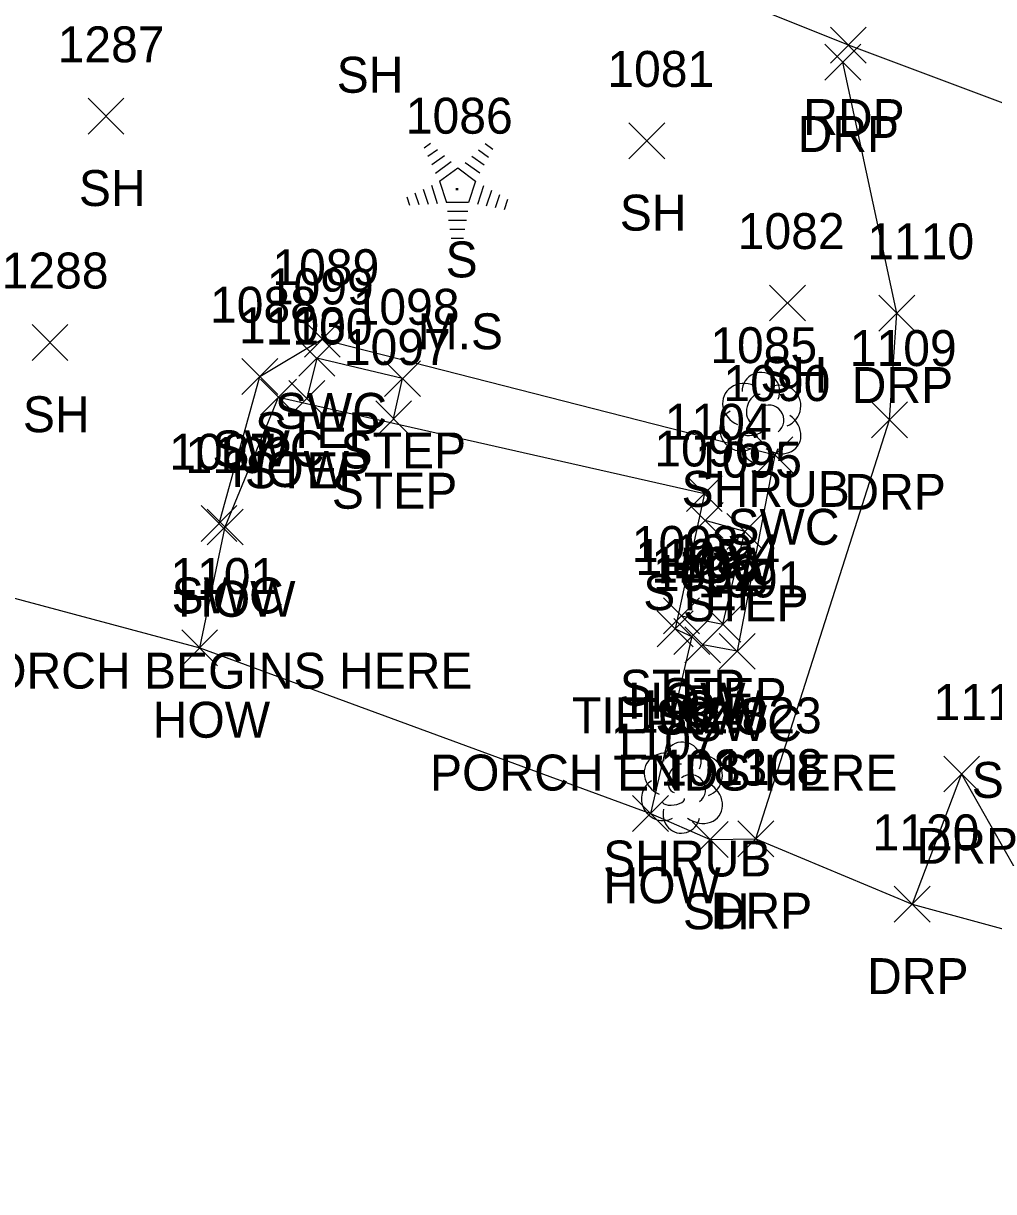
# Model space of a CAD drawing. Extents: x 1616726 to 1619875, y 273782 to 276557.
# Drawn here: x 1617145 to 1617199, y 276075.1 to 276140.1 of the extents above; entities that cross this region are included whole.
import ezdxf

# ---------------------------------------------------------------- set-up
doc = ezdxf.new("R2010")
doc.units = 0
for name, color, linetype in [('L_A', 7, 'Continuous'), ('L_C', 7, 'Continuous'), ('L_I', 7, 'Continuous'), ('L_TIC', 7, 'Continuous'), ('LBC', 7, 'Continuous'), ('LBF', 7, 'Continuous'), ('LSH', 7, 'Continuous'), ('LSOGP', 7, 'Continuous'), ('LTC', 7, 'Continuous'), ('P_A', 7, 'Continuous'), ('P_TIC', 7, 'Continuous'), ('PET', 7, 'Continuous'), ('R_A', 7, 'Continuous'), ('R_I', 7, 'Continuous'), ('R_TIC', 7, 'Continuous'), ('RDP', 7, 'Continuous'), ('RSW', 7, 'Continuous')]:
    doc.layers.add(name, color=color, linetype=linetype)

msp = doc.modelspace()

# ---------------------------------------------------------------- linework, layer by layer
at = {"layer": 'L_TIC'}
for points in [[(1617148.581, 276133.939), (1617150.581, 276135.939)], [(1617150.581, 276133.939), (1617148.581, 276135.939)], [(1617178.684, 276132.57), (1617180.684, 276134.57)], [(1617180.684, 276132.57), (1617178.684, 276134.57)], [(1617186.509, 276123.542), (1617188.509, 276125.542)], [(1617188.509, 276123.542), (1617186.509, 276125.542)], [(1617145.465, 276121.348), (1617147.465, 276123.348)], [(1617147.465, 276121.348), (1617145.465, 276123.348)], [(1617160.313, 276120.462), (1617162.313, 276122.462)], [(1617162.313, 276120.462), (1617160.313, 276122.462)], [(1617165.076, 276119.33), (1617167.076, 276121.33)], [(1617167.076, 276119.33), (1617165.076, 276121.33)], [(1617158.18, 276118.295), (1617160.18, 276120.295)], [(1617160.18, 276118.295), (1617158.18, 276120.295)], [(1617159.754, 276118.227), (1617161.754, 276120.227)], [(1617161.754, 276118.227), (1617159.754, 276120.227)], [(1617164.588, 276117.089), (1617166.588, 276119.089)], [(1617166.588, 276117.089), (1617164.588, 276119.089)], [(1617181.879, 276112.928), (1617183.879, 276114.928)], [(1617183.879, 276112.928), (1617181.879, 276114.928)], [(1617155.207, 276111.073), (1617157.207, 276113.073)], [(1617157.207, 276111.073), (1617155.207, 276113.073)], [(1617181.92, 276111.44), (1617183.92, 276113.44)], [(1617183.92, 276111.44), (1617181.92, 276113.44)], [(1617184.134, 276110.821), (1617186.134, 276112.821)], [(1617186.134, 276110.821), (1617184.134, 276112.821)], [(1617180.613, 276106.128), (1617182.613, 276108.128)], [(1617182.613, 276106.128), (1617180.613, 276108.128)], [(1617180.25, 276105.401), (1617182.25, 276107.401)], [(1617182.25, 276105.401), (1617180.25, 276107.401)], [(1617182.916, 276105.662), (1617184.916, 276107.662)], [(1617184.916, 276105.662), (1617182.916, 276107.662)], [(1617181.183, 276104.971), (1617183.183, 276106.971)], [(1617183.183, 276104.971), (1617181.183, 276106.971)], [(1617153.793, 276104.342), (1617155.793, 276106.342)], [(1617155.793, 276104.342), (1617153.793, 276106.342)], [(1617178.879, 276095.126), (1617180.879, 276097.126)], [(1617180.879, 276095.126), (1617178.879, 276097.126)], [(1617182.196, 276093.677), (1617184.196, 276095.677)], [(1617184.196, 276093.677), (1617182.196, 276095.677)]]:
    msp.add_lwpolyline(points, dxfattribs=at)
at = {"layer": 'LBC'}
msp.add_lwpolyline([(1617154.793, 276105.342), (1617156.207, 276112.073), (1617159.18, 276119.295), (1617182.879, 276113.928), (1617181.25, 276106.401), (1617182.183, 276105.971), (1617179.879, 276096.126)], dxfattribs=at)
at = {"layer": 'LBF'}
for points in [[(1617165.588, 276118.089), (1617166.076, 276120.33), (1617161.313, 276121.462), (1617160.754, 276119.227)], [(1617181.613, 276107.128), (1617183.916, 276106.662), (1617185.134, 276111.821), (1617182.92, 276112.44)]]:
    msp.add_lwpolyline(points, dxfattribs=at)
at = {"layer": 'LSH'}
for p, q in [((1617185.979, 276118.193), (1617185.979, 276118.193)), ((1617185.979, 276118.193), (1617185.979, 276118.193)), ((1617181.614, 276097.616), (1617181.614, 276097.616)), ((1617181.614, 276097.616), (1617181.614, 276097.616))]:
    msp.add_line(p, q, dxfattribs=at)
for centre in [(1617186.026, 276119.627), (1617181.661, 276099.05)]:
    msp.add_arc(centre, 1.047, 335.52715, 180.95627, dxfattribs=at)
for centre, major_axis, ratio, start_param, end_param in [((1617185.187, 276118.86), (1.21, -0.512), 0.895232, 1.570796, 4.712389), ((1617187.021, 276118.777), (-1.141, -0.483), 0.949671, 1.570796, 4.712389), ((1617185.771, 276118.651), (-0.208, -0.792), 0.645439, 3.141593, 6.283185), ((1617186.479, 276118.027), (-0.5, 0.667), 0.989748, 3.141593, 6.283185), ((1617184.896, 276117.485), (0.584, -1.042), 0.959034, 3.141593, 6.283185), ((1617186.979, 276117.36), (-1.09, 0.792), 0.841452, 1.570796, 4.712389), ((1617185.521, 276117.443), (-0.625, -0.083), 0.423636, 0, 3.141593), ((1617185.979, 276116.693), (0.265, 1.061), 0.942809, 1.570796, 4.712389), ((1617180.823, 276098.283), (1.21, -0.512), 0.895232, 1.570796, 4.712389), ((1617182.656, 276098.2), (-1.141, -0.483), 0.949671, 1.570796, 4.712389), ((1617181.406, 276098.075), (-0.208, -0.792), 0.645439, 3.141593, 6.283185), ((1617182.114, 276097.45), (-0.5, 0.667), 0.989748, 3.141593, 6.283185), ((1617180.531, 276096.908), (0.584, -1.042), 0.959034, 3.141593, 6.283185), ((1617182.615, 276096.783), (-1.09, 0.792), 0.841452, 1.570796, 4.712389), ((1617181.156, 276096.866), (-0.625, -0.083), 0.423636, 0, 3.141593), ((1617181.615, 276096.116), (0.265, 1.061), 0.942809, 1.570796, 4.712389)]:
    msp.add_ellipse(centre, major_axis=major_axis, ratio=ratio, start_param=start_param, end_param=end_param, dxfattribs=at)
at = {"layer": 'LSOGP'}
msp.add_lwpolyline([(1617140.035, 276109.296), (1617154.793, 276105.342), (1617179.88, 276096.126), (1617183.196, 276094.677), (1617185.748, 276094.71), (1617194.448, 276091.071), (1617202.547, 276088.865), (1617211.935, 276089.77), (1617218.412, 276086.237), (1617228.114, 276088.354), (1617255.764, 276085.345), (1617277.301, 276080.472), (1617301.293, 276075.073)], dxfattribs=at)
at = {"layer": 'LTC'}
for p, q in [((1617167.288, 276133.173), (1617167.643, 276133.431)), ((1617170.686, 276133.414), (1617171.106, 276133.109)), ((1617167.498, 276132.708), (1617168.027, 276133.092)), ((1617167.707, 276132.242), (1617168.411, 276132.753)), ((1617169.944, 276132.717), (1617170.623, 276132.223)), ((1617170.315, 276133.065), (1617170.865, 276132.666)), ((1617167.917, 276131.776), (1617168.795, 276132.414)), ((1617168.141, 276131.321), (1617169.153, 276132.056)), ((1617169.153, 276132.056), (1617170.15, 276131.331)), ((1617169.573, 276132.369), (1617170.383, 276131.78)), ((1617168.141, 276131.321), (1617168.528, 276130.128)), ((1617170.15, 276131.331), (1617169.759, 276130.128)), ((1617166.776, 276130.669), (1617166.988, 276130.017)), ((1617167.231, 276130.886), (1617167.503, 276130.05)), ((1617167.687, 276131.102), (1617168.018, 276130.083)), ((1617170.588, 276131.06), (1617170.25, 276130.02)), ((1617171.032, 276130.809), (1617170.745, 276129.925)), ((1617166.321, 276130.452), (1617166.473, 276129.984)), ((1617169.759, 276130.128), (1617168.528, 276130.128)), ((1617171.477, 276130.559), (1617171.24, 276129.83)), ((1617171.921, 276130.309), (1617171.734, 276129.735)), ((1617169.721, 276129.628), (1617168.576, 276129.628)), ((1617169.637, 276129.128), (1617168.648, 276129.128)), ((1617169.553, 276128.628), (1617168.721, 276128.628)), ((1617169.469, 276128.128), (1617168.794, 276128.128))]:
    msp.add_line(p, q, dxfattribs=at)
at = {"layer": 'P_TIC'}
for points in [[(1617189.893, 276137.889), (1617191.893, 276139.889)], [(1617191.893, 276137.889), (1617189.893, 276139.889)]]:
    msp.add_lwpolyline(points, dxfattribs=at)
at = {"layer": 'PET'}
msp.add_lwpolyline([(1617343.601, 276102.192), (1617300.74, 276111.108), (1617263.27, 276119.69), (1617236.256, 276126.171), (1617212.86, 276130.651), (1617190.893, 276138.889), (1617148.805, 276155.787), (1617124.366, 276159.729), (1617097.21, 276164.327), (1617058.671, 276171.511)], dxfattribs=at)
at = {"layer": 'R_TIC'}
for points in [[(1617189.58, 276136.948), (1617191.58, 276138.948)], [(1617191.58, 276136.948), (1617189.58, 276138.948)], [(1617192.59, 276122.973), (1617194.59, 276124.973)], [(1617194.59, 276122.973), (1617192.59, 276124.973)], [(1617160.618, 276121.534), (1617162.618, 276123.534)], [(1617162.618, 276121.534), (1617160.618, 276123.534)], [(1617157.137, 276119.443), (1617159.137, 276121.443)], [(1617159.137, 276119.443), (1617157.137, 276121.443)], [(1617192.185, 276117.03), (1617194.185, 276119.03)], [(1617194.185, 276117.03), (1617192.185, 276119.03)], [(1617185.8, 276115.081), (1617187.8, 276117.081)], [(1617187.8, 276115.081), (1617185.8, 276117.081)], [(1617154.869, 276111.26), (1617156.869, 276113.26)], [(1617156.869, 276111.26), (1617154.869, 276113.26)], [(1617181.787, 276104.514), (1617183.787, 276106.514)], [(1617183.787, 276104.514), (1617181.787, 276106.514)], [(1617183.705, 276104.151), (1617185.705, 276106.151)], [(1617185.705, 276104.151), (1617183.705, 276106.151)], [(1617196.199, 276097.323), (1617198.199, 276099.323)], [(1617198.199, 276097.323), (1617196.199, 276099.323)], [(1617184.748, 276093.71), (1617186.748, 276095.71)], [(1617186.748, 276093.71), (1617184.748, 276095.71)], [(1617193.448, 276090.071), (1617195.448, 276092.071)], [(1617195.448, 276090.071), (1617193.448, 276092.071)]]:
    msp.add_lwpolyline(points, dxfattribs=at)
at = {"layer": 'RDP'}
for points in [[(1617185.748, 276094.71), (1617193.185, 276118.03), (1617193.59, 276123.973), (1617190.58, 276137.948)], [(1617202.547, 276088.865), (1617197.199, 276098.323), (1617194.448, 276091.071)]]:
    msp.add_lwpolyline(points, dxfattribs=at)
at = {"layer": 'RSW'}
msp.add_lwpolyline([(1617155.869, 276112.26), (1617158.137, 276120.443), (1617161.618, 276122.534), (1617186.8, 276116.081), (1617184.705, 276105.151), (1617182.787, 276105.514)], dxfattribs=at)

# ---------------------------------------------------------------- texts
at = {"layer": 'L_A'}
for s, p in [('SH', (1617162.418, 276136.244)), ('SH', (1617148.07, 276129.939)), ('SH', (1617178.172, 276128.57)), ('S', (1617168.479, 276125.965)), ('SH', (1617185.998, 276119.542)), ('SH', (1617144.953, 276117.348)), ('STEP', (1617157.872, 276116.462)), ('STEP', (1617162.635, 276115.33)), ('HOW', (1617156.566, 276114.295)), ('STEP', (1617157.313, 276114.227)), ('STEP', (1617162.147, 276113.089)), ('SHRUB', (1617181.609, 276113.193)), ('HOW', (1617180.265, 276108.928)), ('STEP', (1617179.479, 276107.44)), ('HOW', (1617153.593, 276107.073)), ('STEP', (1617181.693, 276106.821)), ('STEP', (1617178.172, 276102.128)), ('HOW', (1617178.636, 276101.401)), ('STEP', (1617180.475, 276101.662)), ('HOW', (1617179.569, 276100.971)), ('HOW', (1617152.178, 276100.342)), ('SHRUB', (1617177.244, 276092.616)), ('HOW', (1617177.265, 276091.126)), ('SH', (1617181.684, 276089.677))]:
    msp.add_text(s, height=2, dxfattribs=at).set_placement(p)
at = {"layer": 'L_C'}
for s, p in [('M.S', (1617166.92, 276121.965)), ('PORCH BEGINS HERE', (1617141.294, 276103.073)), ('TIE=11.823', (1617175.509, 276100.584)), ('PORCH ENDS HERE', (1617167.613, 276097.401)), ('SUMAC CLUMP', (1617197.76, 276096.992))]:
    msp.add_text(s, height=2, dxfattribs=at).set_placement(p)
at = {"layer": 'L_I'}
for s, p in [('1287', (1617146.889, 276137.939)), ('1081', (1617177.479, 276136.57)), ('1086', (1617166.266, 276133.965)), ('1082', (1617184.738, 276127.542)), ('1288', (1617143.772, 276125.348)), ('1099', (1617158.533, 276124.462)), ('1098', (1617163.305, 276123.33)), ('1103', (1617156.976, 276122.295)), ('1100', (1617158.463, 276122.227)), ('1097', (1617162.816, 276121.089)), ('1085', (1617183.208, 276121.193)), ('1104', (1617180.674, 276116.928)), ('1102', (1617154.003, 276115.073)), ('1096', (1617180.093, 276115.44)), ('1095', (1617182.362, 276114.821)), ('1093', (1617178.841, 276110.128)), ('1105', (1617179.046, 276109.401)), ('1094', (1617181.144, 276109.662)), ('1106', (1617179.923, 276108.971)), ('1101', (1617153.155, 276108.342)), ('1084', (1617178.843, 276100.616)), ('1107', (1617177.675, 276099.126)), ('1083', (1617180.425, 276097.677))]:
    msp.add_text(s, height=2, dxfattribs=at).set_placement(p)
at = {"layer": 'LTC'}
msp.add_text('.', height=1.037, rotation=270, dxfattribs=at).set_placement((1617169.036, 276131.069))
at = {"layer": 'P_A'}
msp.add_text('RDP', height=2, dxfattribs=at).set_placement((1617188.381, 276133.889))
at = {"layer": 'R_A'}
for s, p in [('DRP', (1617188.068, 276132.948)), ('DRP', (1617191.079, 276118.973)), ('SWC', (1617158.98, 276117.534)), ('SWC', (1617155.5, 276115.443)), ('DRP', (1617190.673, 276113.03)), ('SWC', (1617184.162, 276111.081)), ('SWC', (1617153.231, 276107.26)), ('SWC', (1617180.15, 276100.514)), ('SWC', (1617182.067, 276100.151)), ('DRP', (1617194.687, 276093.323)), ('DRP', (1617183.236, 276089.71)), ('DRP', (1617191.936, 276086.071))]:
    msp.add_text(s, height=2, dxfattribs=at).set_placement(p)
at = {"layer": 'R_I'}
for s, p in [('1110', (1617191.945, 276126.973)), ('1089', (1617158.839, 276125.534)), ('1088', (1617155.366, 276123.443)), ('1109', (1617190.973, 276121.03)), ('1090', (1617183.941, 276119.081)), ('1087', (1617153.097, 276115.26)), ('1092', (1617180.016, 276108.514)), ('1091', (1617182.5, 276108.151)), ('1119', (1617195.632, 276101.323)), ('1108', (1617183.543, 276097.71)), ('1120', (1617192.235, 276094.071))]:
    msp.add_text(s, height=2, dxfattribs=at).set_placement(p)

doc.saveas('drawing.dxf')
